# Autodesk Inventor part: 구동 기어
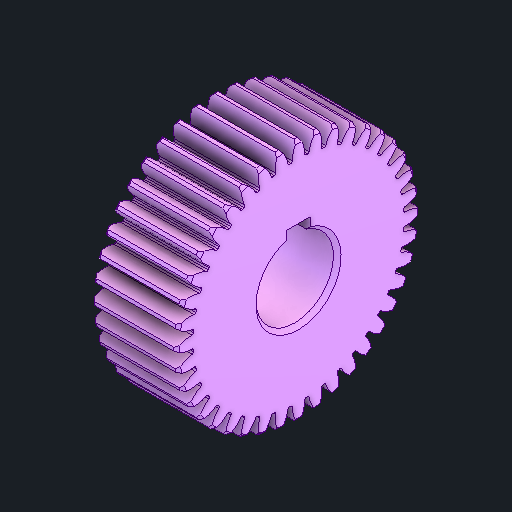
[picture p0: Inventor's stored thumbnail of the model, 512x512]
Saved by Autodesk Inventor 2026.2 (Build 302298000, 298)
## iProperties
Created: 2025-11
Part Number: 구동 기어
Material: 강철, 합금
Document SubType Name: Modeling
Designer: PC2-07
Density: 7.73 g/cm^3
Appearance: 기본값
Author: jhkim
Sending System: Autodesk Inventor 2026
Preprocessor: ST-DEVELOPER v20.1
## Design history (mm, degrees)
feature "솔리드1"
node "솔리드2"
